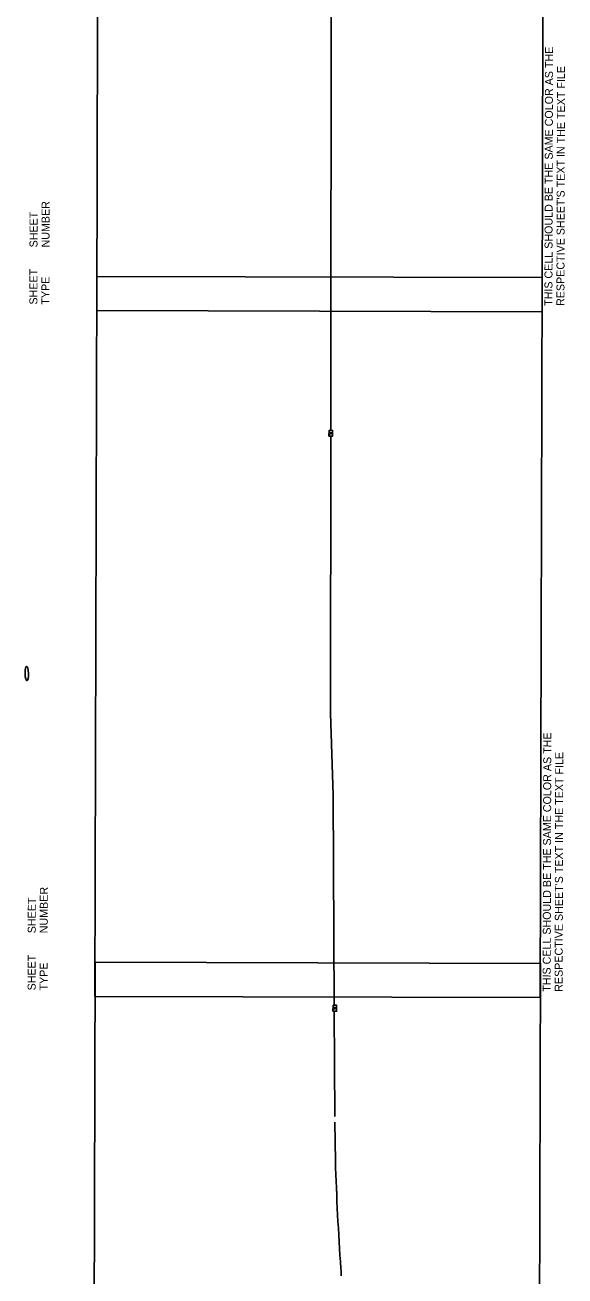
# Model space of a CAD drawing. Extents: x 601462 to 605493, y 331960 to 402715.
# Drawn here: x 602645 to 603827, y 378036 to 380772 of the extents above; entities that cross this region are included whole.
import ezdxf

# ---------------------------------------------------------------- set-up
doc = ezdxf.new("R2010")
doc.units = 0
for name, color, linetype in [('P_FTMS', 7, 'Continuous'), ('P_FTMSConduit', 7, 'Continuous'), ('P_MISC_TXT_1A (Construction)', 7, 'Continuous'), ('P_MISC_TXT_1B (Construction)', 7, 'Continuous')]:
    doc.layers.add(name, color=color, linetype=linetype)

# ---------------------------------------------------------------- blocks, each defined once
blk = doc.blocks.new('FTMS_FCV')
at = {"layer": 'P_FTMS'}
blk.add_line((13, 16), (1, -22), dxfattribs=at)
blk.add_lwpolyline([(39, 24), (-39, 24), (-39, -24), (39, -24)], close=True, dxfattribs=at)
blk.add_lwpolyline([(-12, 16), (1, -22)], dxfattribs=at)

msp = doc.modelspace()

# ---------------------------------------------------------------- linework, layer by layer
at = {"layer": 'P_FTMS'}
msp.add_ellipse((602648.6, 379353.6), major_axis=(-0.4, 16), ratio=0.23471, dxfattribs=at)
at = {"layer": 'P_FTMSConduit'}
for p, q in [((603319.3, 379087.1), (603313.4, 379266.9)), ((603321.7, 378628), (603319.3, 379086.4)), ((603323, 378384.9), (603321.8, 378615.1)), ((603324.3, 378286.9), (603322.7, 378372.1))]:
    msp.add_line(p, q, dxfattribs=at)
for points in [[(603313.8, 379885.4), (603313.9, 380091.4), (603315.5, 381370.6)], [(603313.4, 379266.5), (603313.9, 379872.6)]]:
    msp.add_lwpolyline(points, dxfattribs=at)
for centre, radius, start, end in [((609287, 378472.2), 5965.6, 181.7776, 184.03702), ((603086.9, 378034.6), 250, 0.2997, 4.037)]:
    msp.add_arc(centre, radius, start, end, dxfattribs=at)
at = {"layer": 'P_MISC_TXT_1A (Construction)'}
msp.add_lwpolyline([(603772.7, 378644.6), (603776.7, 380219.6), (602801.8, 380222.1), (602797.7, 378647.1)], close=True, dxfattribs=at)
msp.add_lwpolyline([(603772.7, 378644.6), (603776.7, 380219.6), (602801.8, 380222.1), (602797.7, 378647.1)], close=True, dxfattribs=at)
at = {"layer": 'P_MISC_TXT_1B (Construction)'}
for points in [[(603776.6, 380144.6), (603780.6, 381719.6), (602805.6, 381722.1), (602801.6, 380147.1)], [(603776.6, 380144.6), (603780.6, 381719.6), (602805.6, 381722.1), (602801.6, 380147.1)], [(603768.8, 377144.6), (603772.9, 378719.6), (602797.9, 378722.1), (602793.8, 377147.1)], [(603768.8, 377144.6), (603772.9, 378719.6), (602797.9, 378722.1), (602793.8, 377147.1)]]:
    msp.add_lwpolyline(points, close=True, dxfattribs=at)

# ---------------------------------------------------------------- block references
at = {"layer": 'P_FTMS', "xscale": 0.16404166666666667, "yscale": 0.16404166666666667, "rotation": 88.76248754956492}
for p in [(603314, 379879), (603322.8, 378621.5)]:
    msp.add_blockref('FTMS_FCV', p, dxfattribs=at)

# ---------------------------------------------------------------- texts
at = {"layer": 'P_MISC_TXT_1A (Construction)'}
for s, p in [('THIS CELL SHOULD BE THE SAME COLOR AS THE', (603795.4, 378657.5)), ('THIS CELL SHOULD BE THE SAME COLOR AS THE', (603795.4, 378657.5)), ("RESPECTIVE SHEET'S TEXT IN THE TEXT FILE", (603821.6, 378657.4)), ("RESPECTIVE SHEET'S TEXT IN THE TEXT FILE", (603821.6, 378657.4)), ('NUMBER', (602694.4, 378785.3)), ('NUMBER', (602694.4, 378785.3)), ('SHEET', (602668.2, 378785.4)), ('SHEET', (602668.2, 378785.4)), ('SHEET', (602667.9, 378660.4)), ('SHEET', (602667.9, 378660.4)), ('TYPE', (602694.1, 378660.3)), ('TYPE', (602694.1, 378660.3))]:
    msp.add_text(s, height=17.5, rotation=89.8526, dxfattribs=at).set_placement(p)
at = {"layer": 'P_MISC_TXT_1B (Construction)'}
for s, p in [('THIS CELL SHOULD BE THE SAME COLOR AS THE', (603799.2, 380157.5)), ('THIS CELL SHOULD BE THE SAME COLOR AS THE', (603799.2, 380157.5)), ("RESPECTIVE SHEET'S TEXT IN THE TEXT FILE", (603825.5, 380157.4)), ("RESPECTIVE SHEET'S TEXT IN THE TEXT FILE", (603825.5, 380157.4)), ('NUMBER', (602698.3, 380285.3)), ('NUMBER', (602698.3, 380285.3)), ('SHEET', (602672, 380285.4)), ('SHEET', (602672, 380285.4)), ('SHEET', (602671.7, 380160.4)), ('SHEET', (602671.7, 380160.4)), ('TYPE', (602698, 380160.3)), ('TYPE', (602698, 380160.3))]:
    msp.add_text(s, height=17.5, rotation=89.8526, dxfattribs=at).set_placement(p)

doc.saveas('drawing.dxf')
